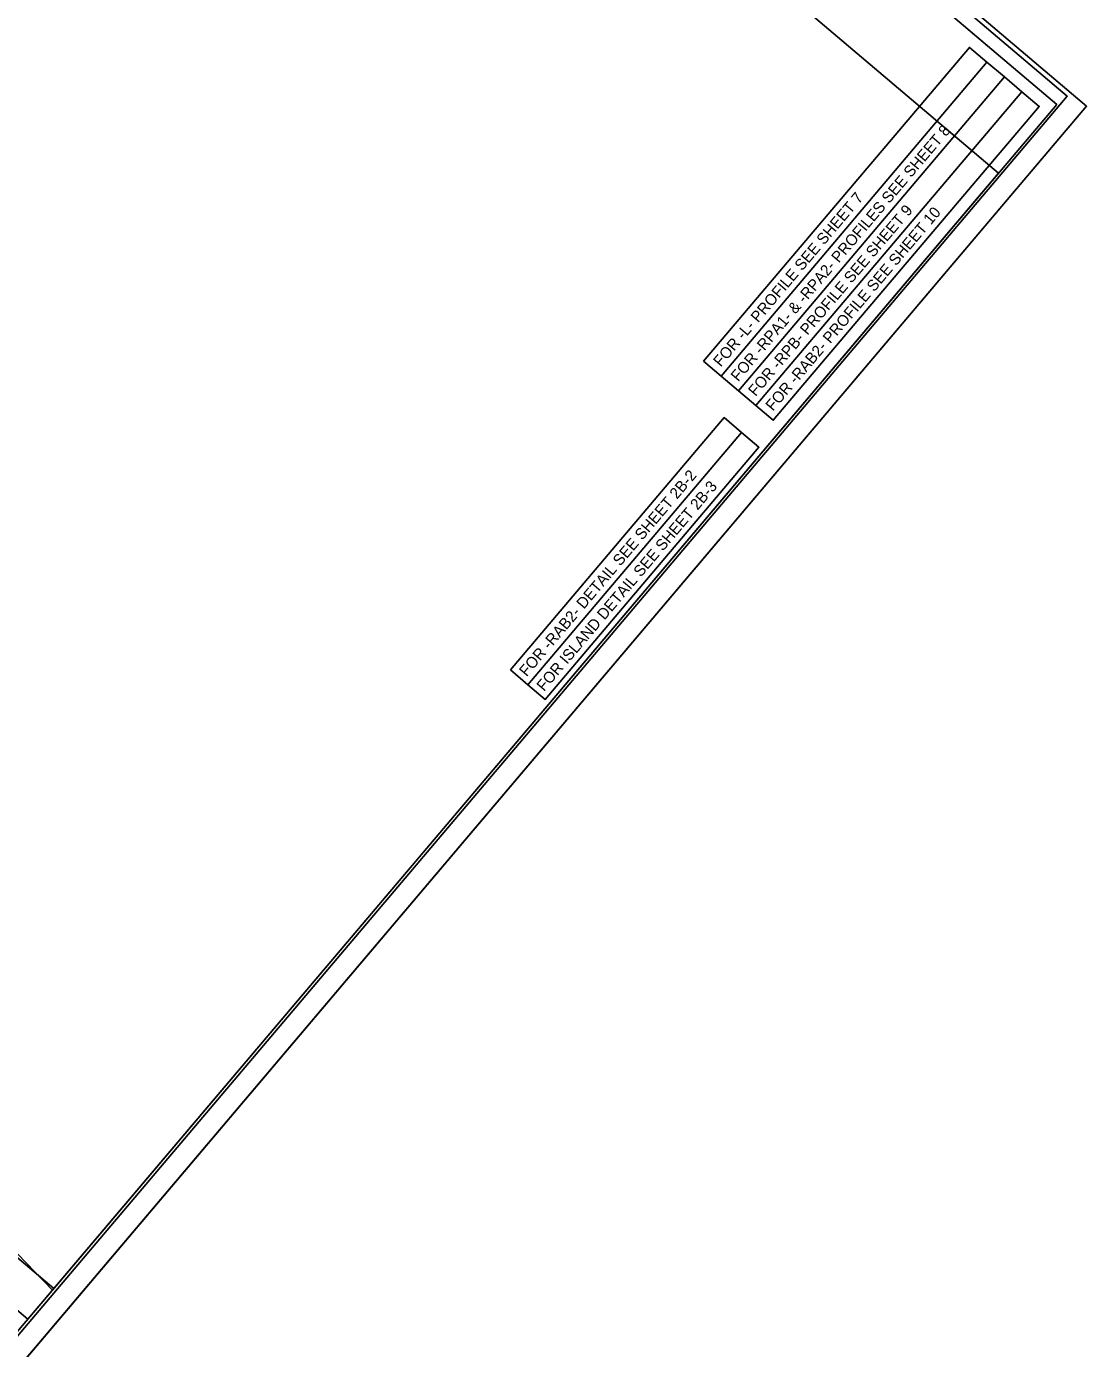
# Model space of a CAD drawing. Extents: x 1761124 to 1763803, y 421930 to 424918.
# Drawn here: x 1762804 to 1763803, y 422941 to 424187 of the extents above; entities that cross this region are included whole.
import ezdxf

# ---------------------------------------------------------------- set-up
doc = ezdxf.new("R2010")
doc.units = 0
for name, color, linetype in [('CTL Primary Horizontal and Vertical Cogo Elevation', 7, 'Continuous'), ('CTL Primary Horizontal and Vertical Cogo Number', 7, 'Continuous'), ('CTL Sheet Datum Description CELL', 7, 'Continuous'), ('Exist Roads Change in Surface', 7, 'Continuous'), ('Exist Roads Change in Surface Text', 7, 'Continuous'), ('Exist Roads EOP Other', 7, 'Continuous'), ('Exist Roads EOP Other Text', 7, 'Continuous'), ('Exist Roads Soil', 7, 'Continuous'), ('Exist Structure Major Deck Tunnel Box Culvert', 7, 'Continuous')]:
    doc.layers.add(name, color=color, linetype=linetype)

msp = doc.modelspace()

# ---------------------------------------------------------------- linework, layer by layer
at = {"layer": 'CTL Primary Horizontal and Vertical Cogo Number'}
msp.add_lwpolyline([(1761925, 421929.5), (1762829.9, 422997.7), (1762190.1, 423539.7), (1762067.8, 423395.3), (1761906.4, 423532), (1761123.8, 422608.2)], close=True, dxfattribs=at)
at = {"layer": 'CTL Sheet Datum Description CELL'}
msp.add_lwpolyline([(1762004.4, 423647.7), (1762290.1, 423405.7), (1762365.1, 423494), (1762431.1, 423438.1), (1762620.9, 423277.3), (1762680.3, 423186), (1762663.1, 423167.9), (1762828.7, 422996.3), (1763720.3, 424048.8), (1763103.2, 424571.6), (1763016.4, 424469), (1762832.3, 424624.9), (1762079.3, 423736.1)], close=True, dxfattribs=at)
at = {"layer": 'Exist Roads Change in Surface'}
msp.add_lwpolyline([(1762715.1, 422827.4), (1763803.3, 424111.9), (1762967.8, 424819.7), (1761879.6, 423535.2)], close=True, dxfattribs=at)
at = {"layer": 'Exist Roads Change in Surface Text'}
msp.add_line((1762715.1, 422827.4), (1763803.3, 424111.9), dxfattribs=at)
at = {"layer": 'Exist Roads EOP Other'}
msp.add_line((1762805.6, 422969), (1762805.6, 422969), dxfattribs=at)
for points in [[(1762974, 424792.2), (1762004.4, 423647.7), (1762805.6, 422969), (1763775.2, 424113.5)], [(1762805.6, 422969), (1762004.4, 423647.7), (1762844.7, 424639.6), (1762959.2, 424542.6), (1763088.5, 424695.2), (1763775.2, 424113.5)]]:
    msp.add_lwpolyline(points, close=True, dxfattribs=at)
at = {"layer": 'Exist Roads EOP Other Text'}
for points in [[(1763442.4, 423871.6), (1763693, 424167.4), (1763709.4, 424153.5), (1763458.8, 423857.7)], [(1763458.8, 423857.7), (1763709.4, 424153.5), (1763725.9, 424139.6), (1763475.3, 423843.8)], [(1763475.3, 423843.8), (1763725.9, 424139.6), (1763742.3, 424125.7), (1763491.7, 423829.9)], [(1763491.7, 423829.9), (1763742.3, 424125.7), (1763758.7, 424111.8), (1763508.1, 423816)], [(1763260.4, 423580.7), (1763461.8, 423818.5), (1763478.2, 423804.6), (1763276.8, 423566.8)], [(1763276.8, 423566.8), (1763478.2, 423804.6), (1763494.6, 423790.6), (1763293.2, 423552.9)]]:
    msp.add_lwpolyline(points, close=True, dxfattribs=at)
at = {"layer": 'Exist Roads Soil'}
msp.add_lwpolyline([(1762708.3, 422850.3), (1763785.2, 424121.4), (1762980.2, 424803.4), (1761903.3, 423532.2)], close=True, dxfattribs=at)
at = {"layer": 'Exist Structure Major Deck Tunnel Box Culvert'}
msp.add_lwpolyline([(1762004.4, 423647.7), (1762805.6, 422969), (1763775.2, 424113.5), (1763135.4, 424655.5), (1762980.7, 424473), (1762819.4, 424609.7)], close=True, dxfattribs=at)

# ---------------------------------------------------------------- texts
at = {"layer": 'CTL Primary Horizontal and Vertical Cogo Elevation'}
for s, p in [('FOR -RPA1- & -RPA2- PROFILES SEE SHEET 8', (1763475, 423851.8)), ('FOR -L- PROFILE SEE SHEET 7', (1763458.5, 423865.7)), ('FOR -RPB- PROFILE SEE SHEET 9', (1763491.4, 423837.9)), ('FOR -RAB2- PROFILE SEE SHEET 10', (1763507.8, 423824)), ('FOR -RAB2- DETAIL SEE SHEET 2B-2', (1763275.6, 423573.8)), ('FOR ISLAND DETAIL SEE SHEET 2B-3', (1763292, 423559.9))]:
    msp.add_text(s, height=10.5, rotation=49.7301, dxfattribs=at).set_placement(p)

doc.saveas('drawing.dxf')
